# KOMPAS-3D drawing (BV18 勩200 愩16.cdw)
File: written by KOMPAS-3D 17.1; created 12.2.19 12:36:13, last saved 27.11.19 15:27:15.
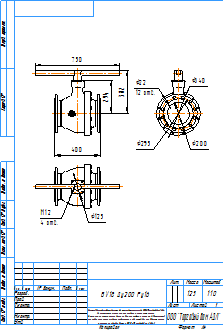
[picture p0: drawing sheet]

Sheet 1: A4, portrait

Title block, sheet 1: name: BV18 Ду200 Ру16; material: Сталь 10  ГОСТ 1050-88; mass: 125; sheets: 1; sheet format: A4; stored path: C:\Users\kka\KOMPAS_Work\!Trash\BV18\KOMPAS 2D\BV18 Ду150 Ру16.cdw

Views: Вид 1, Проекционный вид 2, Проекционный вид 3
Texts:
  kka
  adl
  Рама для чертежей
  Лит-Масса-Масштаб
  Материал-Предприятие
  Масштаб
  Изм.
  Лист
  № докум.
  Подп.
  Дата
  Лит.
  Разраб.
  Пров.
  Т.контр.
  Листов
  Внимание! Данный продукт является объектом авторского права ООО «Торговый Дом АДЛ».
  Запрещается изменение, копирование, распространение
  (в том числе путем копирования на другие сайты и ресурсы в Интернете)
  или любое иное использование информации и объектов без предварительного
  согласия правообладателя (ООО «Торговый Дом АДЛ»).
  Н.контр.
  Утв.
  ООО "Торговый дом АДЛ"
  Изменение
  Номер документа
  Подпись
  Обозначение документа
  Наименование изделия
  Масса изделия по ГОСТ 2.109-73
  Порядковый номер листа
  Общее количество листов в документе
  Характер работы, выполненной лицом, подписавшим документ
  Наименование или индекс предприятия, выпускающего документ
  Инв. № подл.
  Подп. и дата
  Взам. инв. №
  Инв. № дубл.
  Инвентарный номер подлинника по ГОСТ 2.501-68
  Подпись принявшего подлинник в отдел технической документации
  Инвентарный номер подлинника, взамен которого выпущен данный подлинник
  Инвентарный номер дубликата по ГОСТ 2.502-68
  Подпись принявшего дубликат в отдел технической документации
  Справ. №
  Перв. примен.
  Обозначение документа, взамен или на основании которого выпущен данный документ
  Обозначение документа, в котором впервые записан данный документ
  Подпись лица, копировавшего чертеж
  Обозначение формата листа
  !Рама для чертежа
Dimensions and other numbers on the sheet: 750; 294; 400; 382; 295; 200; 22; 12 отв.; 340; 125; 12; 4 отв.; 1:10; 1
